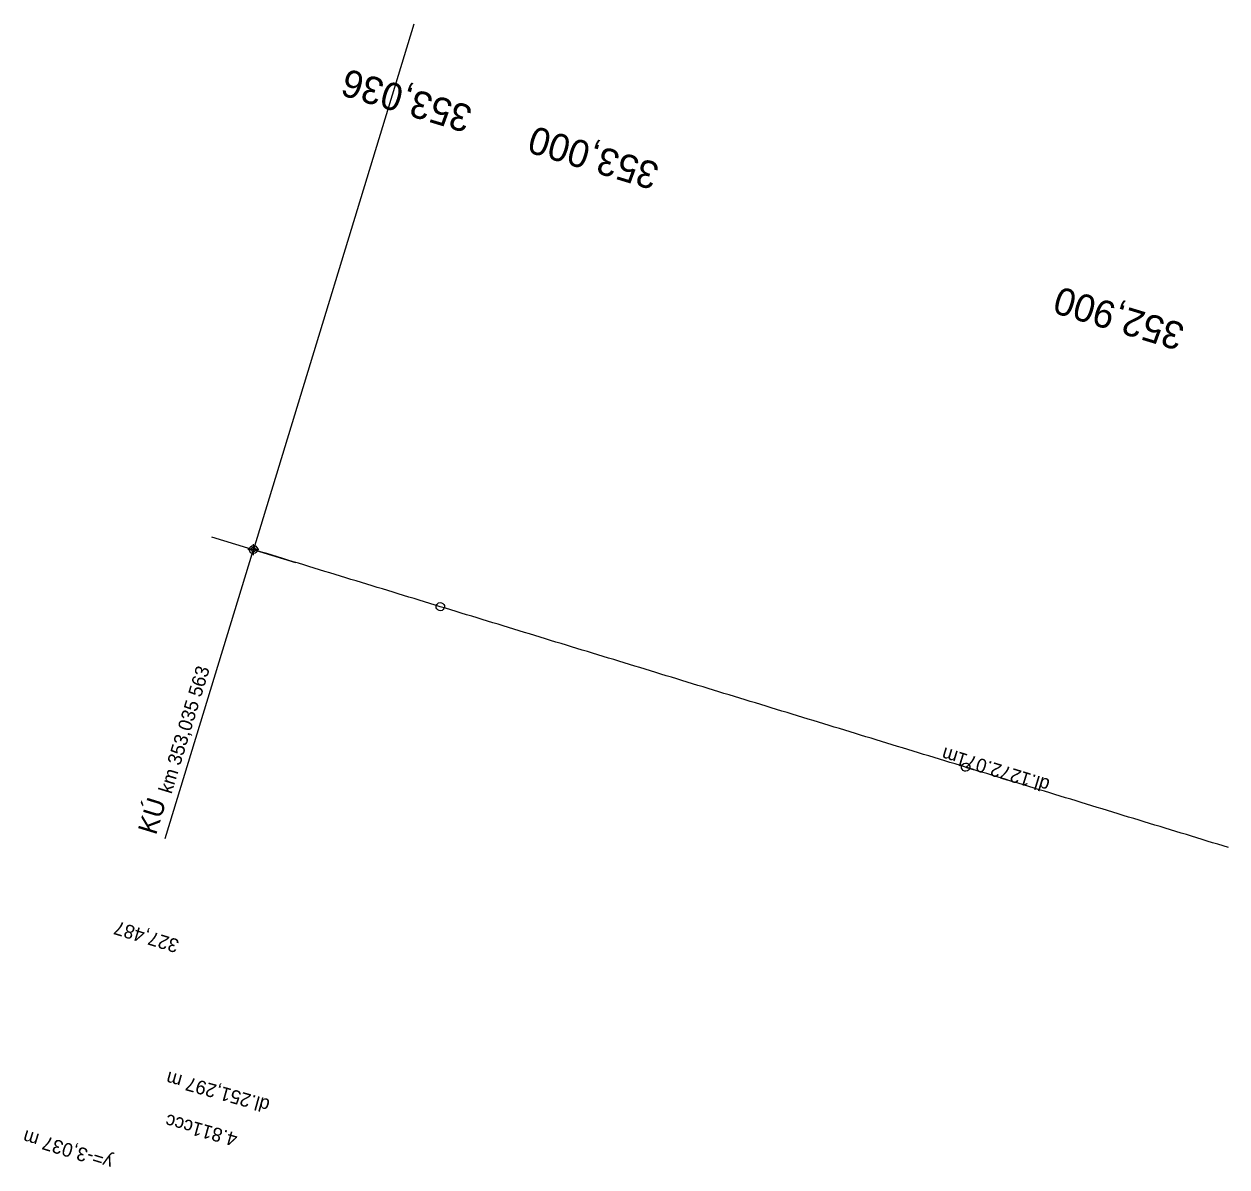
# Model space of a CAD drawing. Extents: x -825429 to 825387, y -1070027 to 1069917.
# Drawn here: x -825429 to -825210.1, y -1069549.8 to -1069341.8 of the extents above; entities that cross this region are included whole.
import ezdxf

# ---------------------------------------------------------------- set-up
doc = ezdxf.new("R2010")
doc.units = 0
doc.layers.add('NEW KOLEJE PALKOBAR', color=7, linetype='Continuous')
doc.layers.add('NEW KOLEJE VLADO PROVI', color=7, linetype='Continuous')

msp = doc.modelspace()

# ---------------------------------------------------------------- linework, layer by layer
at = {"layer": 'NEW KOLEJE PALKOBAR'}
for points in [[(-825387.49, -1069438.17), (-825387.72, -1069438.05), (-825387.91, -1069437.83), (-825388.01, -1069437.65), (-825388.03, -1069437.38), (-825387.95, -1069437.09), (-825387.79, -1069436.93), (-825387.59, -1069436.78), (-825387.31, -1069436.71), (-825387.05, -1069436.74), (-825386.83, -1069436.86), (-825386.63, -1069437.07), (-825386.53, -1069437.26), (-825386.51, -1069437.53), (-825386.6, -1069437.82), (-825386.75, -1069437.98), (-825386.96, -1069438.13), (-825387.24, -1069438.2), (-825387.49, -1069438.17)], [(-825209.81, -1069491.68), (-825210.77, -1069491.39), (-825211.72, -1069491.09), (-825212.68, -1069490.8), (-825213.64, -1069490.51), (-825214.59, -1069490.22), (-825215.55, -1069489.93), (-825216.5, -1069489.63), (-825217.46, -1069489.34), (-825218.42, -1069489.05), (-825219.37, -1069488.76), (-825220.33, -1069488.46), (-825221.29, -1069488.17), (-825222.24, -1069487.88), (-825223.2, -1069487.59), (-825224.15, -1069487.3), (-825225.11, -1069487), (-825226.07, -1069486.71), (-825227.02, -1069486.42), (-825227.98, -1069486.13), (-825228.94, -1069485.83), (-825229.89, -1069485.54), (-825230.85, -1069485.25), (-825231.81, -1069484.96), (-825232.76, -1069484.67), (-825233.72, -1069484.37), (-825234.67, -1069484.08), (-825235.63, -1069483.79), (-825236.59, -1069483.5), (-825237.54, -1069483.2), (-825238.5, -1069482.91), (-825239.46, -1069482.62), (-825240.41, -1069482.33), (-825241.37, -1069482.04), (-825242.33, -1069481.74), (-825243.28, -1069481.45), (-825244.24, -1069481.16), (-825245.19, -1069480.87), (-825246.15, -1069480.57), (-825247.11, -1069480.28), (-825248.06, -1069479.99), (-825249.02, -1069479.7), (-825249.98, -1069479.41), (-825250.93, -1069479.11), (-825251.89, -1069478.82), (-825252.85, -1069478.53), (-825253.8, -1069478.24), (-825254.76, -1069477.94), (-825255.71, -1069477.65), (-825256.67, -1069477.36), (-825257.63, -1069477.07), (-825258.58, -1069476.78), (-825259.54, -1069476.48), (-825260.5, -1069476.19), (-825261.45, -1069475.9), (-825262.41, -1069475.61), (-825263.37, -1069475.31), (-825264.32, -1069475.02), (-825265.28, -1069474.73), (-825266.23, -1069474.44), (-825267.19, -1069474.15), (-825268.15, -1069473.85), (-825269.1, -1069473.56), (-825270.06, -1069473.27), (-825271.02, -1069472.98), (-825271.97, -1069472.68), (-825272.93, -1069472.39), (-825273.89, -1069472.1), (-825274.84, -1069471.81), (-825275.8, -1069471.52), (-825276.75, -1069471.22), (-825277.71, -1069470.93), (-825278.67, -1069470.64), (-825279.62, -1069470.35), (-825280.58, -1069470.05), (-825281.54, -1069469.76), (-825282.49, -1069469.47), (-825283.45, -1069469.18), (-825284.41, -1069468.89), (-825285.36, -1069468.59), (-825286.32, -1069468.3), (-825287.27, -1069468.01), (-825288.23, -1069467.72), (-825289.19, -1069467.42), (-825290.14, -1069467.13), (-825291.1, -1069466.84), (-825292.06, -1069466.55), (-825293.01, -1069466.26), (-825293.97, -1069465.96), (-825294.92, -1069465.67), (-825295.88, -1069465.38), (-825296.84, -1069465.09), (-825297.79, -1069464.8), (-825298.75, -1069464.5), (-825299.71, -1069464.21), (-825300.66, -1069463.92), (-825301.62, -1069463.63), (-825302.58, -1069463.33), (-825303.53, -1069463.04), (-825304.49, -1069462.75), (-825305.44, -1069462.46), (-825306.4, -1069462.17), (-825307.36, -1069461.87), (-825308.31, -1069461.58), (-825309.27, -1069461.29), (-825310.23, -1069461), (-825311.18, -1069460.7), (-825312.14, -1069460.41), (-825313.1, -1069460.12), (-825314.05, -1069459.83), (-825315.01, -1069459.54), (-825315.96, -1069459.24), (-825316.92, -1069458.95), (-825317.88, -1069458.66), (-825318.83, -1069458.37), (-825319.79, -1069458.07), (-825320.75, -1069457.78), (-825321.7, -1069457.49), (-825322.66, -1069457.2), (-825323.62, -1069456.91), (-825324.57, -1069456.61), (-825325.53, -1069456.32), (-825326.48, -1069456.03), (-825327.44, -1069455.74), (-825328.4, -1069455.44), (-825329.35, -1069455.15), (-825330.31, -1069454.86), (-825331.27, -1069454.57), (-825332.22, -1069454.28), (-825333.18, -1069453.98), (-825334.14, -1069453.69), (-825335.09, -1069453.4), (-825336.05, -1069453.11), (-825337, -1069452.81), (-825337.96, -1069452.52), (-825338.92, -1069452.23), (-825339.87, -1069451.94), (-825340.83, -1069451.65), (-825341.79, -1069451.35), (-825342.74, -1069451.06), (-825343.7, -1069450.77), (-825344.66, -1069450.48), (-825345.61, -1069450.18), (-825346.57, -1069449.89), (-825347.52, -1069449.6), (-825348.48, -1069449.31), (-825349.44, -1069449.02), (-825350.39, -1069448.72), (-825351.35, -1069448.43), (-825352.31, -1069448.14), (-825353.26, -1069447.85), (-825354.22, -1069447.55), (-825355.18, -1069447.26), (-825356.13, -1069446.97), (-825357.09, -1069446.68), (-825358.04, -1069446.39), (-825359, -1069446.09), (-825359.96, -1069445.8), (-825360.91, -1069445.51), (-825361.87, -1069445.22), (-825362.83, -1069444.92), (-825363.78, -1069444.63), (-825364.74, -1069444.34), (-825365.69, -1069444.05), (-825366.65, -1069443.76), (-825367.61, -1069443.46), (-825368.56, -1069443.17), (-825369.52, -1069442.88), (-825370.48, -1069442.59), (-825371.43, -1069442.29), (-825372.39, -1069442), (-825373.35, -1069441.71), (-825374.3, -1069441.42), (-825375.26, -1069441.13), (-825376.21, -1069440.83), (-825377.17, -1069440.54), (-825378.13, -1069440.25), (-825379.08, -1069439.96), (-825380.04, -1069439.66), (-825381, -1069439.37), (-825381.95, -1069439.08), (-825382.91, -1069438.79), (-825383.87, -1069438.5), (-825384.82, -1069438.2), (-825385.78, -1069437.91), (-825386.73, -1069437.62), (-825387.27, -1069437.45)], [(-825353.48, -1069448.56), (-825353.71, -1069448.44), (-825353.9, -1069448.23), (-825354, -1069448.04), (-825354.02, -1069447.77), (-825353.94, -1069447.48), (-825353.78, -1069447.32), (-825353.58, -1069447.17), (-825353.3, -1069447.1), (-825353.04, -1069447.13), (-825352.82, -1069447.25), (-825352.62, -1069447.47), (-825352.52, -1069447.65), (-825352.5, -1069447.92), (-825352.59, -1069448.21), (-825352.74, -1069448.37), (-825352.94, -1069448.52), (-825353.23, -1069448.59), (-825353.48, -1069448.56)], [(-825257.85, -1069477.79), (-825258.07, -1069477.66), (-825258.27, -1069477.45), (-825258.37, -1069477.26), (-825258.39, -1069476.99), (-825258.3, -1069476.71), (-825258.15, -1069476.54), (-825257.94, -1069476.4), (-825257.66, -1069476.33), (-825257.41, -1069476.35), (-825257.18, -1069476.47), (-825256.99, -1069476.69), (-825256.89, -1069476.88), (-825256.87, -1069477.14), (-825256.95, -1069477.43), (-825257.11, -1069477.59), (-825257.31, -1069477.74), (-825257.59, -1069477.81), (-825257.85, -1069477.79)]]:
    msp.add_lwpolyline(points, dxfattribs=at)
at = {"layer": 'NEW KOLEJE VLADO PROVI'}
for p, q in [((-825387.27, -1069438.45), (-825387.27, -1069436.45)), ((-825386.27, -1069437.45), (-825388.27, -1069437.45))]:
    msp.add_line(p, q, dxfattribs=at)
for points in [[(-825358.05, -1069341.82), (-825387.27, -1069437.45)], [(-825394.92, -1069435.12), (-825379.62, -1069439.79)], [(-825387.16, -1069437.07), (-825387.04, -1069437.14), (-825386.93, -1069437.25), (-825386.88, -1069437.35), (-825386.87, -1069437.49), (-825386.91, -1069437.65), (-825387, -1069437.73), (-825387.1, -1069437.81), (-825387.25, -1069437.85), (-825387.39, -1069437.84), (-825387.51, -1069437.77), (-825387.61, -1069437.66), (-825387.67, -1069437.56), (-825387.68, -1069437.41), (-825387.63, -1069437.26), (-825387.55, -1069437.17), (-825387.44, -1069437.1), (-825387.29, -1069437.06), (-825387.16, -1069437.07)], [(-825403.34, -1069490.05), (-825387.27, -1069437.45)]]:
    msp.add_lwpolyline(points, dxfattribs=at)

# ---------------------------------------------------------------- texts
at = {"layer": 'NEW KOLEJE PALKOBAR'}
for s, p in [('353,036', (-825347.12, -1069356.9)), ('353,000', (-825313.11, -1069367.29)), ('352,900', (-825217.47, -1069396.51))]:
    msp.add_text(s, height=5, rotation=163.0992, dxfattribs=at).set_placement(p)
at = {"layer": 'NEW KOLEJE VLADO PROVI'}
for s, height, rotation, p in [('km 353,035 563', 2.5, 73.0092, (-825402.2, -1069482.04)), ('dl.1272.071m', 2.5, 163.0092, (-825242.14, -1069479.32)), ('KÚ', 3.5, 73.0092, (-825405.02, -1069489.54)), ('327,487', 2.5, 163.0101, (-825400.62, -1069508.53)), ('dl.251,297 m', 2.5, 164.4526, (-825384.12, -1069537.59)), ('4.811ccc', 2.5, 164.4526, (-825389.99, -1069543.74)), ('y=-3,037 m', 2.5, 163.0101, (-825412.68, -1069547.98))]:
    msp.add_text(s, height=height, rotation=rotation, dxfattribs=at).set_placement(p)

doc.saveas('drawing.dxf')
